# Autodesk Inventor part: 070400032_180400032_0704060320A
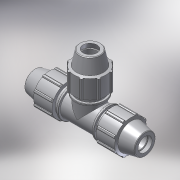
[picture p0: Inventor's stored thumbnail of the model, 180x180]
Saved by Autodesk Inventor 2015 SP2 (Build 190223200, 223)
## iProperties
Created: 2017-02
Part Number: 070400032_180400032_0704060320A
Material: PVC-Piping
Description: PLASSON TEE 32-32-32
Document SubType Name: Modeling
Designer: KIM
Mass: 92.6774 g
Surface Area: 199.44 cm^2
Volume: 66.1981 cm^3
Density: 1.4 g/cm^3
Appearance: Smooth - White
Author: KIM
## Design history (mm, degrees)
derived "07040.ipt"
feature "Solid1::07040.ipt"
tag "TaggingFeature1"
body "Solid1"
other parameters: "d2" = 32, "d4" = 7.75, "d5" = 23.25, "d7" = 64, "d11" = 3.1, "d13" = 120 deg, "d14" = 48, "d15" = 12 deg, "d16" = 55.68, "d18" = 1.6, "d19" = 35 deg, "d20" = 17.5 deg, "d21" = 59.52, "d23" = 0, "d25" = 360 deg, "d27" = 1.28, "d33" = 0.64, "d42" = 32.55, "d43" = 1.92, "d46" = 0.96, "d63" = 67, "d67" = 48, "d76" = 32, "d77" = 64, "d78" = 12 deg, "d79" = 93, "d80" = 120 deg, "d81" = 48, "d82" = 7.75, "d85" = 48, "d86" = 55.68, "d87" = 3.1, "d88" = 3.1, "d89" = 23.25, "d90" = 32.55, "d96" = 4.65, "d98" = 59.52, "d99" = 35 deg, "d100" = 17.5 deg, "d102" = 0, "d103" = 1.28, "d107" = 360 deg, "d109" = 0.96, "d112" = 1.6, "d118" = 360 deg, "d121" = 0, "d128" = 185, "d131" = 28.8, "d132" = 28.8, "d133" = 67, "d134" = 1.34, "d135" = 4.65, "d152" = 0, "d154" = 0, "d156" = 0, "d158" = 0, "d_" = 32, "E_" = 64, "A_" = 93, "l_" = 67, "H_" = 185
